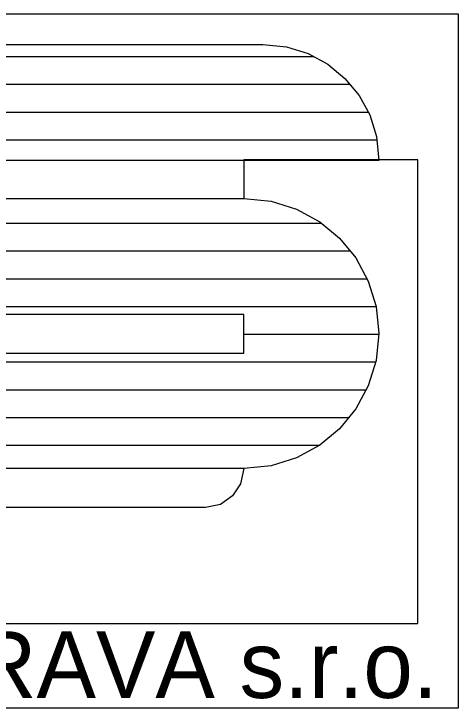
# Model space of a CAD drawing. Extents: x -443494 to -430443, y -1146902 to -1140081.
# Drawn here: x -434877.4 to -434794.2, y -1142916 to -1142786 of the extents above; entities that cross this region are included whole.
import ezdxf

# ---------------------------------------------------------------- set-up
doc = ezdxf.new("R2010")
doc.units = 0
doc.layers.add('Vrstva 1', color=7, linetype='Continuous')

msp = doc.modelspace()

# ---------------------------------------------------------------- linework, layer by layer
at = {"layer": 'Vrstva 1'}
for p, q in [((-434931.386, -1142793.974), (-434821.234, -1142793.974)), ((-434931.386, -1142793.974), (-434821.234, -1142793.974)), ((-434931.386, -1142793.974), (-434821.234, -1142793.974)), ((-434931.386, -1142793.974), (-434821.234, -1142793.974)), ((-434931.386, -1142793.974), (-434821.234, -1142793.974)), ((-434931.386, -1142793.974), (-434821.234, -1142793.974)), ((-434931.386, -1142793.974), (-434821.234, -1142793.974)), ((-434931.386, -1142793.974), (-434821.234, -1142793.974)), ((-434939.004, -1142799.174), (-434814.498, -1142799.174)), ((-434939.004, -1142799.174), (-434814.498, -1142799.174)), ((-434939.004, -1142799.174), (-434814.498, -1142799.174)), ((-434939.004, -1142799.174), (-434814.498, -1142799.174)), ((-434939.004, -1142799.174), (-434814.498, -1142799.174)), ((-434939.004, -1142799.174), (-434814.498, -1142799.174)), ((-434939.004, -1142799.174), (-434814.498, -1142799.174)), ((-434939.004, -1142799.174), (-434814.498, -1142799.174)), ((-434943.187, -1142804.374), (-434811.055, -1142804.374)), ((-434943.187, -1142804.374), (-434811.055, -1142804.374)), ((-434943.187, -1142804.374), (-434811.055, -1142804.374)), ((-434943.187, -1142804.374), (-434811.055, -1142804.374)), ((-434943.187, -1142804.374), (-434811.055, -1142804.374)), ((-434943.187, -1142804.374), (-434811.055, -1142804.374)), ((-434943.187, -1142804.374), (-434811.055, -1142804.374)), ((-434943.187, -1142804.374), (-434811.055, -1142804.374)), ((-434945.455, -1142809.574), (-434809.423, -1142809.574)), ((-434945.455, -1142809.574), (-434809.423, -1142809.574)), ((-434945.455, -1142809.574), (-434809.423, -1142809.574)), ((-434945.455, -1142809.574), (-434809.423, -1142809.574)), ((-434945.455, -1142809.574), (-434809.423, -1142809.574)), ((-434945.455, -1142809.574), (-434809.423, -1142809.574)), ((-434945.455, -1142809.574), (-434809.423, -1142809.574)), ((-434945.455, -1142809.574), (-434809.423, -1142809.574)), ((-434944.963, -1142825.174), (-434819.791, -1142825.174)), ((-434944.963, -1142825.174), (-434819.791, -1142825.174)), ((-434944.963, -1142825.174), (-434819.791, -1142825.174)), ((-434944.963, -1142825.174), (-434819.791, -1142825.174)), ((-434944.963, -1142825.174), (-434819.791, -1142825.174)), ((-434944.963, -1142825.174), (-434819.791, -1142825.174)), ((-434944.963, -1142825.174), (-434819.791, -1142825.174)), ((-434944.963, -1142825.174), (-434819.791, -1142825.174)), ((-434942.465, -1142830.374), (-434814.427, -1142830.374)), ((-434942.465, -1142830.374), (-434814.427, -1142830.374)), ((-434942.465, -1142830.374), (-434814.427, -1142830.374)), ((-434942.465, -1142830.374), (-434814.427, -1142830.374)), ((-434942.465, -1142830.374), (-434814.427, -1142830.374)), ((-434942.465, -1142830.374), (-434814.427, -1142830.374)), ((-434942.465, -1142830.374), (-434814.427, -1142830.374)), ((-434942.465, -1142830.374), (-434814.427, -1142830.374)), ((-434938.099, -1142835.574), (-434811.302, -1142835.574)), ((-434938.099, -1142835.574), (-434811.302, -1142835.574)), ((-434938.099, -1142835.574), (-434811.302, -1142835.574)), ((-434938.099, -1142835.574), (-434811.302, -1142835.574)), ((-434938.099, -1142835.574), (-434811.302, -1142835.574)), ((-434938.099, -1142835.574), (-434811.302, -1142835.574)), ((-434938.099, -1142835.574), (-434811.302, -1142835.574)), ((-434938.099, -1142835.574), (-434811.302, -1142835.574)), ((-434929.436, -1142840.774), (-434809.581, -1142840.774)), ((-434929.436, -1142840.774), (-434809.581, -1142840.774)), ((-434929.436, -1142840.774), (-434809.581, -1142840.774)), ((-434929.436, -1142840.774), (-434809.581, -1142840.774)), ((-434929.436, -1142840.774), (-434809.581, -1142840.774)), ((-434929.436, -1142840.774), (-434809.581, -1142840.774)), ((-434929.436, -1142840.774), (-434809.581, -1142840.774)), ((-434929.436, -1142840.774), (-434809.581, -1142840.774)), ((-434834.349, -1142845.974), (-434809.09, -1142845.974)), ((-434834.349, -1142845.974), (-434809.09, -1142845.974)), ((-434834.349, -1142845.974), (-434809.09, -1142845.974)), ((-434834.349, -1142845.974), (-434809.09, -1142845.974)), ((-434834.349, -1142845.974), (-434809.09, -1142845.974)), ((-434834.349, -1142845.974), (-434809.09, -1142845.974)), ((-434834.349, -1142845.974), (-434809.09, -1142845.974)), ((-434834.349, -1142845.974), (-434809.09, -1142845.974)), ((-434946.432, -1142851.174), (-434809.664, -1142851.174)), ((-434946.432, -1142851.174), (-434809.664, -1142851.174)), ((-434946.432, -1142851.174), (-434809.664, -1142851.174)), ((-434946.432, -1142851.174), (-434809.664, -1142851.174)), ((-434946.432, -1142851.174), (-434809.664, -1142851.174)), ((-434946.432, -1142851.174), (-434809.664, -1142851.174)), ((-434946.432, -1142851.174), (-434809.664, -1142851.174)), ((-434946.432, -1142851.174), (-434809.664, -1142851.174)), ((-434946.432, -1142856.374), (-434811.448, -1142856.374)), ((-434946.432, -1142856.374), (-434811.448, -1142856.374)), ((-434946.432, -1142856.374), (-434811.448, -1142856.374)), ((-434946.432, -1142856.374), (-434811.448, -1142856.374)), ((-434946.432, -1142856.374), (-434811.448, -1142856.374)), ((-434946.432, -1142856.374), (-434811.448, -1142856.374)), ((-434946.432, -1142856.374), (-434811.448, -1142856.374)), ((-434946.432, -1142856.374), (-434811.448, -1142856.374)), ((-434946.432, -1142861.574), (-434814.695, -1142861.574)), ((-434946.432, -1142861.574), (-434814.695, -1142861.574)), ((-434946.432, -1142861.574), (-434814.695, -1142861.574)), ((-434946.432, -1142861.574), (-434814.695, -1142861.574)), ((-434946.432, -1142861.574), (-434814.695, -1142861.574)), ((-434946.432, -1142861.574), (-434814.695, -1142861.574)), ((-434946.432, -1142861.574), (-434814.695, -1142861.574)), ((-434946.432, -1142861.574), (-434814.695, -1142861.574)), ((-434946.432, -1142866.774), (-434820.119, -1142866.774)), ((-434946.432, -1142866.774), (-434820.119, -1142866.774)), ((-434946.432, -1142866.774), (-434820.119, -1142866.774)), ((-434946.432, -1142866.774), (-434820.119, -1142866.774)), ((-434946.432, -1142866.774), (-434820.119, -1142866.774)), ((-434946.432, -1142866.774), (-434820.119, -1142866.774)), ((-434946.432, -1142866.774), (-434820.119, -1142866.774)), ((-434946.432, -1142866.774), (-434820.119, -1142866.774))]:
    msp.add_line(p, q, dxfattribs=at)
for points in [[(-434960.599, -1142884.789), (-434960.599, -1142785.989), (-434794.199, -1142785.989), (-434794.199, -1142915.989), (-434929.399, -1142915.989)], [(-434960.599, -1142884.789), (-434960.599, -1142785.989), (-434794.199, -1142785.989), (-434794.199, -1142915.989), (-434929.399, -1142915.989)], [(-434960.599, -1142884.789), (-434960.599, -1142785.989), (-434794.199, -1142785.989), (-434794.199, -1142915.989), (-434929.399, -1142915.989)], [(-434960.599, -1142884.789), (-434960.599, -1142785.989), (-434794.199, -1142785.989), (-434794.199, -1142915.989), (-434929.399, -1142915.989)], [(-434960.599, -1142884.789), (-434960.599, -1142785.989), (-434794.199, -1142785.989), (-434794.199, -1142915.989), (-434929.399, -1142915.989)], [(-434960.599, -1142884.789), (-434960.599, -1142785.989), (-434794.199, -1142785.989), (-434794.199, -1142915.989), (-434929.399, -1142915.989)], [(-434960.599, -1142884.789), (-434960.599, -1142785.989), (-434794.199, -1142785.989), (-434794.199, -1142915.989), (-434929.399, -1142915.989)], [(-434960.599, -1142884.789), (-434960.599, -1142785.989), (-434794.199, -1142785.989), (-434794.199, -1142915.989), (-434929.399, -1142915.989)], [(-434921.16, -1142791.735), (-434830.781, -1142791.735), (-434826.323, -1142792.131), (-434822.259, -1142793.42), (-434818.593, -1142795.401), (-434815.423, -1142798.077), (-434812.748, -1142801.249), (-434810.761, -1142804.912), (-434809.475, -1142808.979), (-434809.077, -1142813.44), (-434834.349, -1142813.44)], [(-434921.16, -1142791.735), (-434830.781, -1142791.735), (-434826.323, -1142792.131), (-434822.259, -1142793.42), (-434818.593, -1142795.401), (-434815.423, -1142798.077), (-434812.748, -1142801.249), (-434810.761, -1142804.912), (-434809.475, -1142808.979), (-434809.077, -1142813.44), (-434834.349, -1142813.44)], [(-434921.16, -1142791.735), (-434830.781, -1142791.735), (-434826.323, -1142792.131), (-434822.259, -1142793.42), (-434818.593, -1142795.401), (-434815.423, -1142798.077), (-434812.748, -1142801.249), (-434810.761, -1142804.912), (-434809.475, -1142808.979), (-434809.077, -1142813.44), (-434834.349, -1142813.44)], [(-434921.16, -1142791.735), (-434830.781, -1142791.735), (-434826.323, -1142792.131), (-434822.259, -1142793.42), (-434818.593, -1142795.401), (-434815.423, -1142798.077), (-434812.748, -1142801.249), (-434810.761, -1142804.912), (-434809.475, -1142808.979), (-434809.077, -1142813.44), (-434834.349, -1142813.44)], [(-434921.16, -1142791.735), (-434830.781, -1142791.735), (-434826.323, -1142792.131), (-434822.259, -1142793.42), (-434818.593, -1142795.401), (-434815.423, -1142798.077), (-434812.748, -1142801.249), (-434810.761, -1142804.912), (-434809.475, -1142808.979), (-434809.077, -1142813.44), (-434834.349, -1142813.44)], [(-434921.16, -1142791.735), (-434830.781, -1142791.735), (-434826.323, -1142792.131), (-434822.259, -1142793.42), (-434818.593, -1142795.401), (-434815.423, -1142798.077), (-434812.748, -1142801.249), (-434810.761, -1142804.912), (-434809.475, -1142808.979), (-434809.077, -1142813.44), (-434834.349, -1142813.44)], [(-434921.16, -1142791.735), (-434830.781, -1142791.735), (-434826.323, -1142792.131), (-434822.259, -1142793.42), (-434818.593, -1142795.401), (-434815.423, -1142798.077), (-434812.748, -1142801.249), (-434810.761, -1142804.912), (-434809.475, -1142808.979), (-434809.077, -1142813.44), (-434834.349, -1142813.44)], [(-434921.16, -1142791.735), (-434830.781, -1142791.735), (-434826.323, -1142792.131), (-434822.259, -1142793.42), (-434818.593, -1142795.401), (-434815.423, -1142798.077), (-434812.748, -1142801.249), (-434810.761, -1142804.912), (-434809.475, -1142808.979), (-434809.077, -1142813.44), (-434834.349, -1142813.44)], [(-434834.349, -1142813.44), (-434921.16, -1142813.44)], [(-434834.349, -1142813.44), (-434921.16, -1142813.44)], [(-434834.349, -1142813.44), (-434921.16, -1142813.44)], [(-434834.349, -1142813.44), (-434921.16, -1142813.44)], [(-434834.349, -1142813.44), (-434921.16, -1142813.44)], [(-434834.349, -1142813.44), (-434921.16, -1142813.44)], [(-434834.349, -1142813.44), (-434921.16, -1142813.44)], [(-434834.349, -1142813.44), (-434921.16, -1142813.44)], [(-434801.745, -1142900.148), (-434801.745, -1142813.336), (-434809.077, -1142813.336), (-434834.349, -1142813.336), (-434834.349, -1142820.572), (-434829.198, -1142821.066), (-434824.44, -1142822.553), (-434820.08, -1142824.932), (-434816.414, -1142828.005), (-434813.341, -1142831.671), (-434811.063, -1142836.032), (-434809.576, -1142840.79), (-434809.077, -1142845.844), (-434809.576, -1142850.898), (-434811.063, -1142855.654), (-434813.341, -1142859.915), (-434816.414, -1142863.68), (-434820.08, -1142866.751), (-434824.44, -1142869.132), (-434829.198, -1142870.617), (-434834.349, -1142871.111), (-434834.941, -1142873.986), (-434836.431, -1142876.267), (-434838.709, -1142877.85), (-434841.486, -1142878.448), (-434913.924, -1142878.448)], [(-434801.745, -1142900.148), (-434801.745, -1142813.336), (-434809.077, -1142813.336), (-434834.349, -1142813.336), (-434834.349, -1142820.572), (-434829.198, -1142821.066), (-434824.44, -1142822.553), (-434820.08, -1142824.932), (-434816.414, -1142828.005), (-434813.341, -1142831.671), (-434811.063, -1142836.032), (-434809.576, -1142840.79), (-434809.077, -1142845.844), (-434809.576, -1142850.898), (-434811.063, -1142855.654), (-434813.341, -1142859.915), (-434816.414, -1142863.68), (-434820.08, -1142866.751), (-434824.44, -1142869.132), (-434829.198, -1142870.617), (-434834.349, -1142871.111), (-434834.941, -1142873.986), (-434836.431, -1142876.267), (-434838.709, -1142877.85), (-434841.486, -1142878.448), (-434913.924, -1142878.448)], [(-434801.745, -1142900.148), (-434801.745, -1142813.336), (-434809.077, -1142813.336), (-434834.349, -1142813.336), (-434834.349, -1142820.572), (-434829.198, -1142821.066), (-434824.44, -1142822.553), (-434820.08, -1142824.932), (-434816.414, -1142828.005), (-434813.341, -1142831.671), (-434811.063, -1142836.032), (-434809.576, -1142840.79), (-434809.077, -1142845.844), (-434809.576, -1142850.898), (-434811.063, -1142855.654), (-434813.341, -1142859.915), (-434816.414, -1142863.68), (-434820.08, -1142866.751), (-434824.44, -1142869.132), (-434829.198, -1142870.617), (-434834.349, -1142871.111), (-434834.941, -1142873.986), (-434836.431, -1142876.267), (-434838.709, -1142877.85), (-434841.486, -1142878.448), (-434913.924, -1142878.448)], [(-434801.745, -1142900.148), (-434801.745, -1142813.336), (-434809.077, -1142813.336), (-434834.349, -1142813.336), (-434834.349, -1142820.572), (-434829.198, -1142821.066), (-434824.44, -1142822.553), (-434820.08, -1142824.932), (-434816.414, -1142828.005), (-434813.341, -1142831.671), (-434811.063, -1142836.032), (-434809.576, -1142840.79), (-434809.077, -1142845.844), (-434809.576, -1142850.898), (-434811.063, -1142855.654), (-434813.341, -1142859.915), (-434816.414, -1142863.68), (-434820.08, -1142866.751), (-434824.44, -1142869.132), (-434829.198, -1142870.617), (-434834.349, -1142871.111), (-434834.941, -1142873.986), (-434836.431, -1142876.267), (-434838.709, -1142877.85), (-434841.486, -1142878.448), (-434913.924, -1142878.448)], [(-434801.745, -1142900.148), (-434801.745, -1142813.336), (-434809.077, -1142813.336), (-434834.349, -1142813.336), (-434834.349, -1142820.572), (-434829.198, -1142821.066), (-434824.44, -1142822.553), (-434820.08, -1142824.932), (-434816.414, -1142828.005), (-434813.341, -1142831.671), (-434811.063, -1142836.032), (-434809.576, -1142840.79), (-434809.077, -1142845.844), (-434809.576, -1142850.898), (-434811.063, -1142855.654), (-434813.341, -1142859.915), (-434816.414, -1142863.68), (-434820.08, -1142866.751), (-434824.44, -1142869.132), (-434829.198, -1142870.617), (-434834.349, -1142871.111), (-434834.941, -1142873.986), (-434836.431, -1142876.267), (-434838.709, -1142877.85), (-434841.486, -1142878.448), (-434913.924, -1142878.448)], [(-434801.745, -1142900.148), (-434801.745, -1142813.336), (-434809.077, -1142813.336), (-434834.349, -1142813.336), (-434834.349, -1142820.572), (-434829.198, -1142821.066), (-434824.44, -1142822.553), (-434820.08, -1142824.932), (-434816.414, -1142828.005), (-434813.341, -1142831.671), (-434811.063, -1142836.032), (-434809.576, -1142840.79), (-434809.077, -1142845.844), (-434809.576, -1142850.898), (-434811.063, -1142855.654), (-434813.341, -1142859.915), (-434816.414, -1142863.68), (-434820.08, -1142866.751), (-434824.44, -1142869.132), (-434829.198, -1142870.617), (-434834.349, -1142871.111), (-434834.941, -1142873.986), (-434836.431, -1142876.267), (-434838.709, -1142877.85), (-434841.486, -1142878.448), (-434913.924, -1142878.448)], [(-434801.745, -1142900.148), (-434801.745, -1142813.336), (-434809.077, -1142813.336), (-434834.349, -1142813.336), (-434834.349, -1142820.572), (-434829.198, -1142821.066), (-434824.44, -1142822.553), (-434820.08, -1142824.932), (-434816.414, -1142828.005), (-434813.341, -1142831.671), (-434811.063, -1142836.032), (-434809.576, -1142840.79), (-434809.077, -1142845.844), (-434809.576, -1142850.898), (-434811.063, -1142855.654), (-434813.341, -1142859.915), (-434816.414, -1142863.68), (-434820.08, -1142866.751), (-434824.44, -1142869.132), (-434829.198, -1142870.617), (-434834.349, -1142871.111), (-434834.941, -1142873.986), (-434836.431, -1142876.267), (-434838.709, -1142877.85), (-434841.486, -1142878.448), (-434913.924, -1142878.448)], [(-434801.745, -1142900.148), (-434801.745, -1142813.336), (-434809.077, -1142813.336), (-434834.349, -1142813.336), (-434834.349, -1142820.572), (-434829.198, -1142821.066), (-434824.44, -1142822.553), (-434820.08, -1142824.932), (-434816.414, -1142828.005), (-434813.341, -1142831.671), (-434811.063, -1142836.032), (-434809.576, -1142840.79), (-434809.077, -1142845.844), (-434809.576, -1142850.898), (-434811.063, -1142855.654), (-434813.341, -1142859.915), (-434816.414, -1142863.68), (-434820.08, -1142866.751), (-434824.44, -1142869.132), (-434829.198, -1142870.617), (-434834.349, -1142871.111), (-434834.941, -1142873.986), (-434836.431, -1142876.267), (-434838.709, -1142877.85), (-434841.486, -1142878.448), (-434913.924, -1142878.448)], [(-434921.16, -1142820.572), (-434834.349, -1142820.572), (-434829.198, -1142821.066), (-434824.44, -1142822.553), (-434820.08, -1142824.932), (-434816.414, -1142828.005), (-434813.341, -1142831.671), (-434811.063, -1142836.032), (-434809.576, -1142840.79), (-434809.077, -1142845.844), (-434809.576, -1142850.898), (-434811.063, -1142855.654), (-434813.341, -1142859.915), (-434816.414, -1142863.68), (-434820.08, -1142866.751), (-434824.44, -1142869.132), (-434829.198, -1142870.617), (-434834.349, -1142871.111), (-434921.16, -1142871.111)], [(-434921.16, -1142820.572), (-434834.349, -1142820.572), (-434829.198, -1142821.066), (-434824.44, -1142822.553), (-434820.08, -1142824.932), (-434816.414, -1142828.005), (-434813.341, -1142831.671), (-434811.063, -1142836.032), (-434809.576, -1142840.79), (-434809.077, -1142845.844), (-434809.576, -1142850.898), (-434811.063, -1142855.654), (-434813.341, -1142859.915), (-434816.414, -1142863.68), (-434820.08, -1142866.751), (-434824.44, -1142869.132), (-434829.198, -1142870.617), (-434834.349, -1142871.111), (-434921.16, -1142871.111)], [(-434921.16, -1142820.572), (-434834.349, -1142820.572), (-434829.198, -1142821.066), (-434824.44, -1142822.553), (-434820.08, -1142824.932), (-434816.414, -1142828.005), (-434813.341, -1142831.671), (-434811.063, -1142836.032), (-434809.576, -1142840.79), (-434809.077, -1142845.844), (-434809.576, -1142850.898), (-434811.063, -1142855.654), (-434813.341, -1142859.915), (-434816.414, -1142863.68), (-434820.08, -1142866.751), (-434824.44, -1142869.132), (-434829.198, -1142870.617), (-434834.349, -1142871.111), (-434921.16, -1142871.111)], [(-434921.16, -1142820.572), (-434834.349, -1142820.572), (-434829.198, -1142821.066), (-434824.44, -1142822.553), (-434820.08, -1142824.932), (-434816.414, -1142828.005), (-434813.341, -1142831.671), (-434811.063, -1142836.032), (-434809.576, -1142840.79), (-434809.077, -1142845.844), (-434809.576, -1142850.898), (-434811.063, -1142855.654), (-434813.341, -1142859.915), (-434816.414, -1142863.68), (-434820.08, -1142866.751), (-434824.44, -1142869.132), (-434829.198, -1142870.617), (-434834.349, -1142871.111), (-434921.16, -1142871.111)], [(-434921.16, -1142820.572), (-434834.349, -1142820.572), (-434829.198, -1142821.066), (-434824.44, -1142822.553), (-434820.08, -1142824.932), (-434816.414, -1142828.005), (-434813.341, -1142831.671), (-434811.063, -1142836.032), (-434809.576, -1142840.79), (-434809.077, -1142845.844), (-434809.576, -1142850.898), (-434811.063, -1142855.654), (-434813.341, -1142859.915), (-434816.414, -1142863.68), (-434820.08, -1142866.751), (-434824.44, -1142869.132), (-434829.198, -1142870.617), (-434834.349, -1142871.111), (-434921.16, -1142871.111)], [(-434921.16, -1142820.572), (-434834.349, -1142820.572), (-434829.198, -1142821.066), (-434824.44, -1142822.553), (-434820.08, -1142824.932), (-434816.414, -1142828.005), (-434813.341, -1142831.671), (-434811.063, -1142836.032), (-434809.576, -1142840.79), (-434809.077, -1142845.844), (-434809.576, -1142850.898), (-434811.063, -1142855.654), (-434813.341, -1142859.915), (-434816.414, -1142863.68), (-434820.08, -1142866.751), (-434824.44, -1142869.132), (-434829.198, -1142870.617), (-434834.349, -1142871.111), (-434921.16, -1142871.111)], [(-434921.16, -1142820.572), (-434834.349, -1142820.572), (-434829.198, -1142821.066), (-434824.44, -1142822.553), (-434820.08, -1142824.932), (-434816.414, -1142828.005), (-434813.341, -1142831.671), (-434811.063, -1142836.032), (-434809.576, -1142840.79), (-434809.077, -1142845.844), (-434809.576, -1142850.898), (-434811.063, -1142855.654), (-434813.341, -1142859.915), (-434816.414, -1142863.68), (-434820.08, -1142866.751), (-434824.44, -1142869.132), (-434829.198, -1142870.617), (-434834.349, -1142871.111), (-434921.16, -1142871.111)], [(-434921.16, -1142820.572), (-434834.349, -1142820.572), (-434829.198, -1142821.066), (-434824.44, -1142822.553), (-434820.08, -1142824.932), (-434816.414, -1142828.005), (-434813.341, -1142831.671), (-434811.063, -1142836.032), (-434809.576, -1142840.79), (-434809.077, -1142845.844), (-434809.576, -1142850.898), (-434811.063, -1142855.654), (-434813.341, -1142859.915), (-434816.414, -1142863.68), (-434820.08, -1142866.751), (-434824.44, -1142869.132), (-434829.198, -1142870.617), (-434834.349, -1142871.111), (-434921.16, -1142871.111)], [(-434921.16, -1142849.51), (-434834.349, -1142849.51), (-434834.349, -1142842.277), (-434921.16, -1142842.277)], [(-434921.16, -1142849.51), (-434834.349, -1142849.51), (-434834.349, -1142842.277), (-434921.16, -1142842.277)], [(-434921.16, -1142849.51), (-434834.349, -1142849.51), (-434834.349, -1142842.277), (-434921.16, -1142842.277)], [(-434921.16, -1142849.51), (-434834.349, -1142849.51), (-434834.349, -1142842.277), (-434921.16, -1142842.277)], [(-434921.16, -1142849.51), (-434834.349, -1142849.51), (-434834.349, -1142842.277), (-434921.16, -1142842.277)], [(-434921.16, -1142849.51), (-434834.349, -1142849.51), (-434834.349, -1142842.277), (-434921.16, -1142842.277)], [(-434921.16, -1142849.51), (-434834.349, -1142849.51), (-434834.349, -1142842.277), (-434921.16, -1142842.277)], [(-434921.16, -1142849.51), (-434834.349, -1142849.51), (-434834.349, -1142842.277), (-434921.16, -1142842.277)], [(-434928.297, -1142900.148), (-434801.745, -1142900.148)], [(-434928.297, -1142900.148), (-434801.745, -1142900.148)], [(-434928.297, -1142900.148), (-434801.745, -1142900.148)], [(-434928.297, -1142900.148), (-434801.745, -1142900.148)], [(-434928.297, -1142900.148), (-434801.745, -1142900.148)], [(-434928.297, -1142900.148), (-434801.745, -1142900.148)], [(-434928.297, -1142900.148), (-434801.745, -1142900.148)], [(-434928.297, -1142900.148), (-434801.745, -1142900.148)]]:
    msp.add_lwpolyline(points, dxfattribs=at)

# ---------------------------------------------------------------- texts
msp.add_text('OSTRAVA s.r.o.', height=12.48, dxfattribs=at).set_placement((-434919.514, -1142914.084))
msp.add_text('OSTRAVA s.r.o.', height=12.48, dxfattribs=at).set_placement((-434919.514, -1142914.084))
msp.add_text('OSTRAVA s.r.o.', height=12.48, dxfattribs=at).set_placement((-434919.514, -1142914.084))
msp.add_text('OSTRAVA s.r.o.', height=12.48, dxfattribs=at).set_placement((-434919.514, -1142914.084))
msp.add_text('OSTRAVA s.r.o.', height=12.48, dxfattribs=at).set_placement((-434919.514, -1142914.084))
msp.add_text('OSTRAVA s.r.o.', height=12.48, dxfattribs=at).set_placement((-434919.514, -1142914.084))
msp.add_text('OSTRAVA s.r.o.', height=12.48, dxfattribs=at).set_placement((-434919.514, -1142914.084))
msp.add_text('OSTRAVA s.r.o.', height=12.48, dxfattribs=at).set_placement((-434919.514, -1142914.084))

doc.saveas('drawing.dxf')
